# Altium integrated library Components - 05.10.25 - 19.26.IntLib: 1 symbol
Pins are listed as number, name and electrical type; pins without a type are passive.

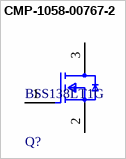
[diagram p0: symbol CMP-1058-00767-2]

## CMP-1058-00767-2
designator Q?, comment BSS138LT1G
Manufacturer Lifecycle Status: ACTIVE; NexarPartId: 5035; Input Capacitance: 50pF; Element Configuration: Single; Voltage Rating (DC): 50V; Continuous Drain Current (ID): 200mA; Turn-On Delay Time: 20ns; Nominal Vgs: 1.5V; Max Junction Temperature (Tj): 150°C; Number of Channels: 1; Gate to Source Voltage (Vgs): 20V; Drain to Source Resistance: 3.5Ω; Max Power Dissipation: 225mW
footprint FP-318-IPC_A
footprint FP-318-IPC_C
footprint FP-318-MFG
footprint FP-318-IPC_B
pins: 1 G, 2 S, 3 D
